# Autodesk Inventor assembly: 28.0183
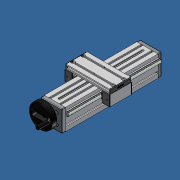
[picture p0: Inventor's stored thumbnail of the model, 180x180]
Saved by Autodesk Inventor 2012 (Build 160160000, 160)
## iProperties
Created: 2007-06
Part Number: 28.0183
Document SubType Name: Assembly
Designer: Andy Moles
Description: ADJUSTING UNIT VEW 90
Author: Andy Moles
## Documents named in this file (19)
- C:\Andys Backup Data\ANDY'S INVENTOR\INVENTOR LIBRARIES\PARTS LIBRARY\READY FOR USE MODULES LG\28.0183 ADJUSTING UNIT VEW 90.iam
- C:\Andys Backup Data\ANDY'S INVENTOR\INVENTOR LIBRARIES\PARTS LIBRARY\FASTENING ELEMENTS\NUTS\21.1351 M8 SQUARE NUT.ipt
- C:\Andys Backup Data\ANDY'S INVENTOR\INVENTOR LIBRARIES\PARTS LIBRARY\READY FOR USE MODULES LG\SUBCOMPONENTS\50.1264 BALL BEARING 10X30X9 6200 2RS DIN 625.ipt
- C:\Andys Backup Data\ANDY'S INVENTOR\INVENTOR LIBRARIES\PARTS LIBRARY\READY FOR USE MODULES LG\SUBCOMPONENTS\28.0204 HANDWHEEL 100mm.iam
- C:\Andys Backup Data\ANDY'S INVENTOR\INVENTOR LIBRARIES\PARTS LIBRARY\READY FOR USE MODULES LG\SUBCOMPONENTS\28.0205 BEARING PLATE 90X90 HANDWHEEL SIDE.ipt
- C:\Andys Backup Data\ANDY'S INVENTOR\INVENTOR LIBRARIES\PARTS LIBRARY\READY FOR USE MODULES LG\SUBCOMPONENTS\28.0206 BEARING PLATE 90X90 IDLER SIDE.ipt
- C:\Andys Backup Data\ANDY'S INVENTOR\INVENTOR LIBRARIES\PARTS LIBRARY\FASTENING ELEMENTS\SCREWS CAP\21.1204 M8X25.ipt
- C:\Andys Backup Data\ANDY'S INVENTOR\INVENTOR LIBRARIES\PARTS LIBRARY\READY FOR USE MODULES LG\SUBCOMPONENTS\28.0216 90x90 rail.iam
- C:\Andys Backup Data\ANDY'S INVENTOR\INVENTOR LIBRARIES\PARTS LIBRARY\READY FOR USE MODULES LG\SUBCOMPONENTS\28.0221 ACME SCREW 16X4.ipt
- C:\Andys Backup Data\ANDY'S INVENTOR\INVENTOR LIBRARIES\PARTS LIBRARY\FASTENING ELEMENTS\WASHERS\21.1326 DISC SPRING 20.ipt
- C:\Andys Backup Data\ANDY'S INVENTOR\INVENTOR LIBRARIES\PARTS LIBRARY\READY FOR USE MODULES LG\SUBCOMPONENTS\28.0225_1 LWG 32X45-90 90X19-NSC.ipt
- C:\Andys Backup Data\ANDY'S INVENTOR\INVENTOR LIBRARIES\PARTS LIBRARY\READY FOR USE MODULES LG\SUBCOMPONENTS\28.0126 SLIDE 45X32.ipt
- C:\Andys Backup Data\ANDY'S INVENTOR\INVENTOR LIBRARIES\PARTS LIBRARY\FASTENING ELEMENTS\SCREWS CAP\21.1200 M8X16.ipt
- C:\Andys Backup Data\ANDY'S INVENTOR\INVENTOR LIBRARIES\PARTS LIBRARY\FASTENING ELEMENTS\SCREWS CAP\21.1235 M5X16.ipt
- C:\Andys Backup Data\ANDY'S INVENTOR\INVENTOR LIBRARIES\PARTS LIBRARY\COMPONENTS LG\22.1094 SLIDE RAIL LG.iam
- C:\Andys Backup Data\ANDY'S INVENTOR\INVENTOR LIBRARIES\PARTS LIBRARY\END CAPS\22.1003_1 END CAP 45x32 Z Gray.iam
- C:\Andys Backup Data\ANDY'S INVENTOR\INVENTOR LIBRARIES\PARTS LIBRARY\END CAPS\22.1014_1 END CAP 90X19 GRAY.ipt
- C:\Andys Backup Data\ANDY'S INVENTOR\INVENTOR LIBRARIES\PARTS LIBRARY\READY FOR USE MODULES LG\SUBCOMPONENTS\28.0257 BRONZE NUT 16X4 NOTCHED.ipt
- C:\Andys Backup Data\ANDY'S INVENTOR\INVENTOR LIBRARIES\PARTS LIBRARY\READY FOR USE MODULES LG\SUBCOMPONENTS\28.0255 Nut slide connector 20.ipt
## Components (40 placed, 18 different names)
1. 28.0216 90x90 rail:1 [sub-assembly] — Flush:4, Mate:14, Mate:15, Mate:17, Angle:2, Angle:3, Flush:5, Flush:6, Flush:7, Mate:18, Flush:8, Angle:13, Mate:28, Angle:15
2. 50.1264 10X30X9 6200 2RS DIN 625 BALL BEARING:1 — Insert:15
3. 50.1264 10X30X9 6200 2RS DIN 625 BALL BEARING:2 — Insert:14, Insert:18
4. 28.0204 HANDWHEEL 100mm:1 [sub-assembly] — Insert:5
5. 28.0205 BEARING PLATE 90X90 HANDWHEEL SIDE:1 — Insert:5, Insert:6, Insert:7, Insert:8, Insert:9, Insert:15, Angle:3, Flush:7, Mate:18, Flush:8, Angle:14
6. 28.0206 BEARING PLATE 90X90 IDLER SIDE:1 — Insert:10, Insert:11, Insert:12, Insert:13, Insert:14, Mate:17, Angle:2, Flush:5, Flush:6
7. 21.1204  M8 x 25:1 — Insert:6
8. 21.1204  M8 x 25:2 — Insert:7
9. 21.1204  M8 x 25:3 — Insert:8
10. 21.1204  M8 x 25:4 — Insert:13
11. 21.1204  M8 x 25:5 — Insert:9
12. 21.1204  M8 x 25:6 — Insert:12
13. 21.1204  M8 x 25:7 — Insert:11
14. 21.1204  M8 x 25:8 — Insert:10
15. 28.0221 ACME SCREW 16X4:1 — Insert:16, Insert:17, Mate:27
16. 21.1326 DISC SPRING 20:1 — Insert:16
17. 21.1326 DISC SPRING 20:2 — Insert:17, Insert:18
18. 28.0225_1 LWG 32X45-90 90X19-NSC:1 — Mate:19, Flush:9, Flush:10, Mate:20, Flush:11, Flush:12, Insert:19, Insert:20, Insert:21, Insert:22, Insert:23, Insert:24, Insert:25, Insert:26, Angle:5, Angle:6, Angle:7, Angle:8, Insert:27, Insert:28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
19. 28.0126 SLIDE 45X32:1 — Mate:19, Flush:9, Flush:10, Mate:23, Flush:14, Mate:24, Insert:29, Insert:31, Angle:11, Angle:12
20. 28.0126 SLIDE 45X32:2 — Mate:20, Flush:11, Flush:12, Mate:21, Flush:13, Mate:22, Insert:30, Insert:32, Angle:9, Angle:10
21. 21.1200 M8 x 16:1 — Insert:19
22. 21.1200 M8 x 16:2 — Insert:20
23. 21.1200 M8 x 16:3 — Insert:22
24. 21.1200 M8 x 16:4 — Insert:21
25. 21.1351 M8 SQUARE NUT:2 — Insert:24, Angle:8
26. 21.1351 M8 SQUARE NUT:3 — Insert:23, Angle:7
27. 21.1351 M8 SQUARE NUT:4 — Insert:25, Angle:6
28. 21.1351 M8 SQUARE NUT:5 — Insert:26, Angle:5
29. 21.1235  M5 x 16:1 — Insert:27
30. 21.1235  M5 x 16:2 — Insert:28
31. 22.1094 SLIDE RAIL LG:1 [sub-assembly] — Mate:21, Flush:13, Mate:22
32. 22.1094 SLIDE RAIL LG:2 [sub-assembly] — Mate:23, Flush:14, Mate:24, Mate:28
33. 22.1003\1 END CAP 45x32 Z Gray:1 [sub-assembly] — Insert:29, Angle:11
34. 22.1003\1 END CAP 45x32 Z Gray:2 [sub-assembly] — Insert:32, Angle:9
35. 22.1003\1 END CAP 45x32 Z Gray:3 [sub-assembly] — Insert:31, Angle:12
36. 22.1003\1 END CAP 45x32 Z Gray:4 [sub-assembly] — Insert:30, Angle:10
37. 22.1014_1 END CAP 90X19 GRAY:1 — Mate:25, Flush:15, Flush:16
38. 22.1014_1 END CAP 90X19 GRAY:2 — Mate:26, Flush:17, Flush:18
39. 28.0257 BRONZE NUT 16X4 NOTCHED:1 — Mate:27, Angle:13, Mate:29
40. 28.0255 Nut slide connector 20:1 — Insert:33, Angle:16, Mate:29
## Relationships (73: Insert 29, Flush 15, Mate 15, Angle 14)
- Insert:5: 28.0204 HANDWHEEL 100mm:1 ↔ 28.0205 BEARING PLATE 90X90 HANDWHEEL SIDE:1
- Insert:6: 28.0205 BEARING PLATE 90X90 HANDWHEEL SIDE:1 ↔ 21.1204  M8 x 25:1
- Insert:7: 28.0205 BEARING PLATE 90X90 HANDWHEEL SIDE:1 ↔ 21.1204  M8 x 25:2
- Insert:8: 28.0205 BEARING PLATE 90X90 HANDWHEEL SIDE:1 ↔ 21.1204  M8 x 25:3
- Insert:9: 28.0205 BEARING PLATE 90X90 HANDWHEEL SIDE:1 ↔ 21.1204  M8 x 25:5
- Insert:10: 28.0206 BEARING PLATE 90X90 IDLER SIDE:1 ↔ 21.1204  M8 x 25:8
- Insert:11: 28.0206 BEARING PLATE 90X90 IDLER SIDE:1 ↔ 21.1204  M8 x 25:7
- Insert:12: 28.0206 BEARING PLATE 90X90 IDLER SIDE:1 ↔ 21.1204  M8 x 25:6
- Insert:13: 28.0206 BEARING PLATE 90X90 IDLER SIDE:1 ↔ 21.1204  M8 x 25:4
- Insert:14: 50.1264 10X30X9 6200 2RS DIN 625 BALL BEARING:2 ↔ 28.0206 BEARING PLATE 90X90 IDLER SIDE:1
- Insert:15: 50.1264 10X30X9 6200 2RS DIN 625 BALL BEARING:1 ↔ 28.0205 BEARING PLATE 90X90 HANDWHEEL SIDE:1
- Flush:4: 28.0216 90x90 rail:1
- Mate:14: 28.0216 90x90 rail:1
- Mate:15: 28.0216 90x90 rail:1
- Mate:17: 28.0216 90x90 rail:1 ↔ 28.0206 BEARING PLATE 90X90 IDLER SIDE:1
- Angle:2: 28.0216 90x90 rail:1 ↔ 28.0206 BEARING PLATE 90X90 IDLER SIDE:1
- Angle:3: 28.0216 90x90 rail:1 ↔ 28.0205 BEARING PLATE 90X90 HANDWHEEL SIDE:1
- Flush:5: 28.0216 90x90 rail:1 ↔ 28.0206 BEARING PLATE 90X90 IDLER SIDE:1
- Flush:6: 28.0216 90x90 rail:1 ↔ 28.0206 BEARING PLATE 90X90 IDLER SIDE:1
- Flush:7: 28.0216 90x90 rail:1 ↔ 28.0205 BEARING PLATE 90X90 HANDWHEEL SIDE:1
- Mate:18: 28.0216 90x90 rail:1 ↔ 28.0205 BEARING PLATE 90X90 HANDWHEEL SIDE:1
- Flush:8: 28.0216 90x90 rail:1 ↔ 28.0205 BEARING PLATE 90X90 HANDWHEEL SIDE:1
- Insert:16: 28.0221 ACME SCREW 16X4:1 ↔ 21.1326 DISC SPRING 20:1
- Insert:17: 28.0221 ACME SCREW 16X4:1 ↔ 21.1326 DISC SPRING 20:2
- Insert:18: 50.1264 10X30X9 6200 2RS DIN 625 BALL BEARING:2 ↔ 21.1326 DISC SPRING 20:2
- Mate:19: 28.0225_1 LWG 32X45-90 90X19-NSC:1 ↔ 28.0126 SLIDE 45X32:1
- Flush:9: 28.0225_1 LWG 32X45-90 90X19-NSC:1 ↔ 28.0126 SLIDE 45X32:1
- Flush:10: 28.0225_1 LWG 32X45-90 90X19-NSC:1 ↔ 28.0126 SLIDE 45X32:1
- Mate:20: 28.0225_1 LWG 32X45-90 90X19-NSC:1 ↔ 28.0126 SLIDE 45X32:2
- Flush:11: 28.0225_1 LWG 32X45-90 90X19-NSC:1 ↔ 28.0126 SLIDE 45X32:2
- Flush:12: 28.0225_1 LWG 32X45-90 90X19-NSC:1 ↔ 28.0126 SLIDE 45X32:2
- Insert:19: 28.0225_1 LWG 32X45-90 90X19-NSC:1 ↔ 21.1200 M8 x 16:1
- Insert:20: 28.0225_1 LWG 32X45-90 90X19-NSC:1 ↔ 21.1200 M8 x 16:2
- Insert:21: 28.0225_1 LWG 32X45-90 90X19-NSC:1 ↔ 21.1200 M8 x 16:4
- Insert:22: 28.0225_1 LWG 32X45-90 90X19-NSC:1 ↔ 21.1200 M8 x 16:3
- Insert:23: 28.0225_1 LWG 32X45-90 90X19-NSC:1 ↔ 21.1351 M8 SQUARE NUT:3
- Insert:24: 28.0225_1 LWG 32X45-90 90X19-NSC:1 ↔ 21.1351 M8 SQUARE NUT:2
- Insert:25: 28.0225_1 LWG 32X45-90 90X19-NSC:1 ↔ 21.1351 M8 SQUARE NUT:4
- Insert:26: 28.0225_1 LWG 32X45-90 90X19-NSC:1 ↔ 21.1351 M8 SQUARE NUT:5
- Angle:5: 28.0225_1 LWG 32X45-90 90X19-NSC:1 ↔ 21.1351 M8 SQUARE NUT:5
- Angle:6: 28.0225_1 LWG 32X45-90 90X19-NSC:1 ↔ 21.1351 M8 SQUARE NUT:4
- Angle:7: 28.0225_1 LWG 32X45-90 90X19-NSC:1 ↔ 21.1351 M8 SQUARE NUT:3
- Angle:8: 28.0225_1 LWG 32X45-90 90X19-NSC:1 ↔ 21.1351 M8 SQUARE NUT:2
- Insert:27: 28.0225_1 LWG 32X45-90 90X19-NSC:1 ↔ 21.1235  M5 x 16:1
- Insert:28: 28.0225_1 LWG 32X45-90 90X19-NSC:1 ↔ 21.1235  M5 x 16:2
- Mate:21: 28.0126 SLIDE 45X32:2 ↔ 22.1094 SLIDE RAIL LG:1
- Flush:13: 28.0126 SLIDE 45X32:2 ↔ 22.1094 SLIDE RAIL LG:1
- Mate:22: 28.0126 SLIDE 45X32:2 ↔ 22.1094 SLIDE RAIL LG:1
- Mate:23: 28.0126 SLIDE 45X32:1 ↔ 22.1094 SLIDE RAIL LG:2
- Flush:14: 28.0126 SLIDE 45X32:1 ↔ 22.1094 SLIDE RAIL LG:2
- Mate:24: 28.0126 SLIDE 45X32:1 ↔ 22.1094 SLIDE RAIL LG:2
- Insert:29: 28.0126 SLIDE 45X32:1 ↔ 22.1003\1 END CAP 45x32 Z Gray:1
- Insert:30: 28.0126 SLIDE 45X32:2 ↔ 22.1003\1 END CAP 45x32 Z Gray:4
- Insert:31: 28.0126 SLIDE 45X32:1 ↔ 22.1003\1 END CAP 45x32 Z Gray:3
- Insert:32: 28.0126 SLIDE 45X32:2 ↔ 22.1003\1 END CAP 45x32 Z Gray:2
- Angle:9: 28.0126 SLIDE 45X32:2 ↔ 22.1003\1 END CAP 45x32 Z Gray:2
- Angle:10: 28.0126 SLIDE 45X32:2 ↔ 22.1003\1 END CAP 45x32 Z Gray:4
- Angle:11: 28.0126 SLIDE 45X32:1 ↔ 22.1003\1 END CAP 45x32 Z Gray:1
- Angle:12: 28.0126 SLIDE 45X32:1 ↔ 22.1003\1 END CAP 45x32 Z Gray:3
- Mate:25: 28.0225_1 LWG 32X45-90 90X19-NSC:1 ↔ 22.1014_1 END CAP 90X19 GRAY:1
- Flush:15: 28.0225_1 LWG 32X45-90 90X19-NSC:1 ↔ 22.1014_1 END CAP 90X19 GRAY:1
- Flush:16: 28.0225_1 LWG 32X45-90 90X19-NSC:1 ↔ 22.1014_1 END CAP 90X19 GRAY:1
- Mate:26: 28.0225_1 LWG 32X45-90 90X19-NSC:1 ↔ 22.1014_1 END CAP 90X19 GRAY:2
- Flush:17: 28.0225_1 LWG 32X45-90 90X19-NSC:1 ↔ 22.1014_1 END CAP 90X19 GRAY:2
- Flush:18: 28.0225_1 LWG 32X45-90 90X19-NSC:1 ↔ 22.1014_1 END CAP 90X19 GRAY:2
- Mate:27: 28.0221 ACME SCREW 16X4:1 ↔ 28.0257 BRONZE NUT 16X4 NOTCHED:1
- Angle:13: 28.0216 90x90 rail:1 ↔ 28.0257 BRONZE NUT 16X4 NOTCHED:1
- Angle:14: 28.0205 BEARING PLATE 90X90 HANDWHEEL SIDE:1 ↔ 28.0225_1 LWG 32X45-90 90X19-NSC:1
- Mate:28: 28.0216 90x90 rail:1 ↔ 22.1094 SLIDE RAIL LG:2
- Angle:15: 28.0216 90x90 rail:1 ↔ 28.0225_1 LWG 32X45-90 90X19-NSC:1
- Insert:33: 28.0225_1 LWG 32X45-90 90X19-NSC:1 ↔ 28.0255 Nut slide connector 20:1
- Angle:16: 28.0225_1 LWG 32X45-90 90X19-NSC:1 ↔ 28.0255 Nut slide connector 20:1
- Mate:29: 28.0257 BRONZE NUT 16X4 NOTCHED:1 ↔ 28.0255 Nut slide connector 20:1
